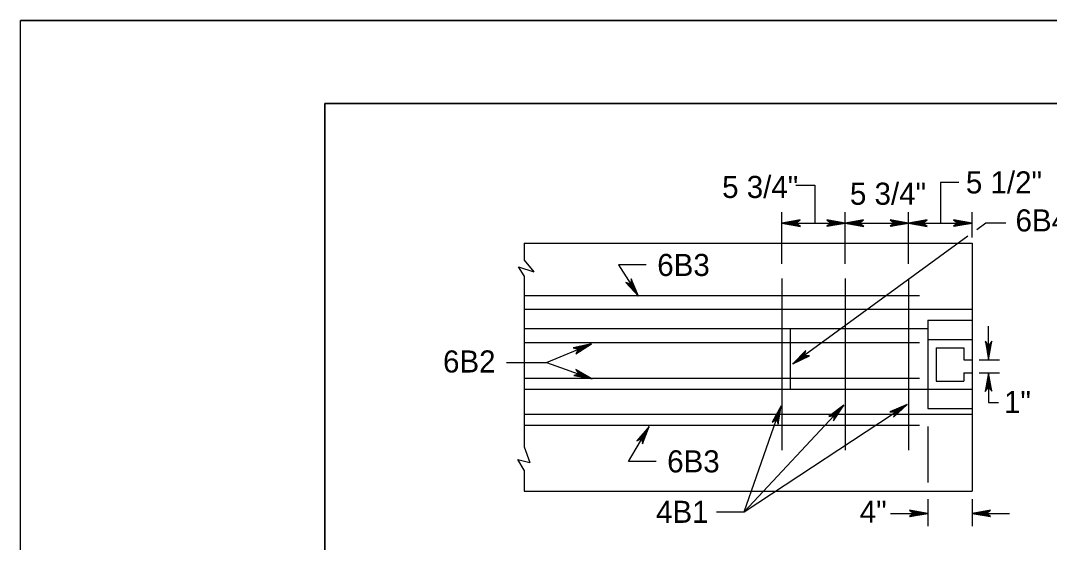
# Model space of a CAD drawing. Extents: x 499883 to 500983, y 499104 to 499764.
# Drawn here: x 499934.8 to 500121.3, y 499669.1 to 499763.6 of the extents above; entities that cross this region are included whole.
import ezdxf

# ---------------------------------------------------------------- set-up
doc = ezdxf.new("R2010")
doc.units = 0
for name, color, linetype in [('1', 7, 'Continuous'), ('24', 7, 'Continuous'), ('41', 7, 'Continuous'), ('5', 7, 'Continuous')]:
    doc.layers.add(name, color=color, linetype=linetype)

msp = doc.modelspace()

# ---------------------------------------------------------------- linework, layer by layer
at = {"layer": '1'}
for p, q in [((500982.94, 499763.64), (499934.77, 499763.64)), ((499989.94, 499748.64), (499989.94, 499118.64)), ((499989.94, 499748.64), (499989.94, 499118.64)), ((500979.94, 499748.64), (499989.94, 499748.64))]:
    msp.add_line(p, q, dxfattribs=at)
at = {"layer": '24'}
for points in [[(500072.77, 499726.96), (500076.12, 499726.37), (500075.32, 499726.96), (500076.1, 499727.54), (500072.77, 499726.96), (500072.99, 499726.97), (500076.03, 499726.41), (500075.26, 499726.97), (500075.97, 499727.5), (500073.11, 499726.98), (500073.22, 499726.96), (500075.82, 499726.5), (500075.24, 499726.97), (500075.84, 499727.42), (500073.28, 499726.96), (500073.39, 499726.98), (500075.66, 499726.57), (500075.22, 499726.96), (500075.67, 499727.37), (500073.71, 499726.98), (500073.9, 499726.98), (500075.49, 499726.65), (500075.18, 499726.95), (500075.51, 499727.28), (500073.93, 499726.96), (500074.11, 499726.95), (500075.31, 499726.74), (500075.08, 499726.98), (500075.33, 499727.21), (500074.28, 499726.96), (500074.44, 499726.94), (500075.16, 499726.8), (500075.04, 499726.97), (500075.24, 499727.15), (500074.53, 499726.96), (500075, 499726.85), (500074.93, 499726.98), (500075.14, 499727.1), (500074.65, 499726.98), (500074.96, 499726.9), (500074.83, 499727), (500074.98, 499727.06), (500074.83, 499726.97), (500074.91, 499726.95)], [(500084.26, 499726.96), (500080.91, 499727.55), (500081.71, 499726.96), (500080.93, 499726.38), (500084.26, 499726.96), (500084.04, 499726.95), (500081.01, 499727.51), (500081.77, 499726.95), (500081.06, 499726.42), (500083.92, 499726.94), (500083.81, 499726.96), (500081.21, 499727.42), (500081.79, 499726.95), (500081.19, 499726.5), (500083.76, 499726.96), (500083.64, 499726.94), (500081.37, 499727.35), (500081.82, 499726.96), (500081.36, 499726.55), (500083.32, 499726.94), (500083.13, 499726.94), (500081.54, 499727.27), (500081.85, 499726.97), (500081.52, 499726.64), (500083.1, 499726.96), (500082.92, 499726.97), (500081.72, 499727.17), (500081.95, 499726.94), (500081.7, 499726.71), (500082.76, 499726.96), (500082.59, 499726.98), (500081.87, 499727.11), (500081.99, 499726.95), (500081.79, 499726.77), (500082.5, 499726.96), (500082.03, 499727.07), (500082.1, 499726.94), (500081.89, 499726.81), (500082.38, 499726.94), (500082.07, 499727.02), (500082.2, 499726.92), (500082.05, 499726.86), (500082.2, 499726.95), (500082.13, 499726.97)], [(500084.26, 499726.96), (500087.61, 499726.37), (500086.81, 499726.96), (500087.59, 499727.54), (500084.26, 499726.96), (500084.48, 499726.97), (500087.52, 499726.41), (500086.75, 499726.97), (500087.46, 499727.5), (500084.6, 499726.98), (500084.72, 499726.96), (500087.31, 499726.5), (500086.73, 499726.97), (500087.33, 499727.42), (500084.77, 499726.96), (500084.88, 499726.98), (500087.15, 499726.57), (500086.71, 499726.96), (500087.16, 499727.37), (500085.2, 499726.98), (500085.39, 499726.98), (500086.98, 499726.65), (500086.67, 499726.95), (500087, 499727.28), (500085.42, 499726.96), (500085.6, 499726.95), (500086.8, 499726.74), (500086.57, 499726.98), (500086.82, 499727.21), (500085.77, 499726.96), (500085.94, 499726.94), (500086.65, 499726.8), (500086.54, 499726.97), (500086.73, 499727.15), (500086.02, 499726.96), (500086.49, 499726.85), (500086.42, 499726.98), (500086.63, 499727.1), (500086.14, 499726.98), (500086.45, 499726.9), (500086.32, 499727), (500086.47, 499727.06), (500086.32, 499726.97), (500086.4, 499726.95)], [(500095.75, 499726.96), (500092.4, 499727.55), (500093.2, 499726.96), (500092.42, 499726.38), (500095.75, 499726.96), (500095.53, 499726.95), (500092.5, 499727.51), (500093.27, 499726.95), (500092.56, 499726.42), (500095.41, 499726.94), (500095.3, 499726.96), (500092.7, 499727.42), (500093.28, 499726.95), (500092.68, 499726.5), (500095.25, 499726.96), (500095.14, 499726.94), (500092.86, 499727.35), (500093.31, 499726.96), (500092.86, 499726.55), (500094.81, 499726.94), (500094.62, 499726.94), (500093.03, 499727.27), (500093.34, 499726.97), (500093.01, 499726.64), (500094.59, 499726.96), (500094.41, 499726.97), (500093.22, 499727.17), (500093.45, 499726.94), (500093.2, 499726.71), (500094.25, 499726.96), (500094.08, 499726.98), (500093.36, 499727.11), (500093.48, 499726.95), (500093.28, 499726.77), (500093.99, 499726.96), (500093.52, 499727.07), (500093.59, 499726.94), (500093.38, 499726.81), (500093.87, 499726.94), (500093.57, 499727.02), (500093.69, 499726.92), (500093.55, 499726.86), (500093.69, 499726.95), (500093.62, 499726.97)], [(500095.75, 499726.96), (500099.1, 499726.37), (500098.3, 499726.96), (500099.09, 499727.54), (500095.75, 499726.96), (500095.98, 499726.97), (500099.01, 499726.41), (500098.24, 499726.97), (500098.95, 499727.5), (500096.1, 499726.98), (500096.21, 499726.96), (500098.81, 499726.5), (500098.22, 499726.97), (500098.82, 499727.42), (500096.26, 499726.96), (500096.37, 499726.98), (500098.64, 499726.57), (500098.2, 499726.96), (500098.65, 499727.37), (500096.69, 499726.98), (500096.88, 499726.98), (500098.47, 499726.65), (500098.16, 499726.95), (500098.5, 499727.28), (500096.92, 499726.96), (500097.09, 499726.95), (500098.29, 499726.74), (500098.06, 499726.98), (500098.31, 499727.21), (500097.26, 499726.96), (500097.43, 499726.94), (500098.15, 499726.8), (500098.03, 499726.97), (500098.22, 499727.15), (500097.51, 499726.96), (500097.98, 499726.85), (500097.92, 499726.98), (500098.12, 499727.1), (500097.63, 499726.98), (500097.94, 499726.9), (500097.81, 499727), (500097.96, 499727.06), (500097.81, 499726.97), (500097.89, 499726.95)], [(500107.24, 499726.96), (500103.89, 499727.55), (500104.69, 499726.96), (500103.91, 499726.38), (500107.24, 499726.96), (500107.02, 499726.95), (500103.99, 499727.51), (500104.76, 499726.95), (500104.05, 499726.42), (500106.9, 499726.94), (500106.79, 499726.96), (500104.19, 499727.42), (500104.77, 499726.95), (500104.17, 499726.5), (500106.74, 499726.96), (500106.63, 499726.94), (500104.36, 499727.35), (500104.8, 499726.96), (500104.35, 499726.55), (500106.3, 499726.94), (500106.11, 499726.94), (500104.52, 499727.27), (500104.83, 499726.97), (500104.5, 499726.64), (500106.08, 499726.96), (500105.9, 499726.97), (500104.71, 499727.17), (500104.94, 499726.94), (500104.69, 499726.71), (500105.74, 499726.96), (500105.57, 499726.98), (500104.85, 499727.11), (500104.97, 499726.95), (500104.77, 499726.77), (500105.48, 499726.96), (500105.01, 499727.07), (500105.08, 499726.94), (500104.88, 499726.81), (500105.36, 499726.94), (500105.06, 499727.02), (500105.19, 499726.92), (500105.04, 499726.86), (500105.18, 499726.95), (500105.11, 499726.97)], [(500046.76, 499713.71), (500045.47, 499716.86), (500045.4, 499715.87), (500044.49, 499716.22), (500046.76, 499713.71), (500046.64, 499713.89), (500045.49, 499716.76), (500045.43, 499715.81), (500044.6, 499716.13), (500046.57, 499713.99), (500046.52, 499714.09), (500045.52, 499716.54), (500045.44, 499715.79), (500044.73, 499716.06), (500046.49, 499714.14), (500046.42, 499714.22), (500045.55, 499716.36), (500045.46, 499715.78), (500044.87, 499715.94), (500046.25, 499714.5), (500046.15, 499714.66), (500045.57, 499716.17), (500045.48, 499715.75), (500045.02, 499715.86), (500046.14, 499714.69), (500046.05, 499714.85), (500045.59, 499715.97), (500045.52, 499715.65), (500045.19, 499715.74), (500045.96, 499714.98), (500045.88, 499715.13), (500045.61, 499715.82), (500045.54, 499715.63), (500045.29, 499715.7), (500045.82, 499715.2), (500045.67, 499715.66), (500045.59, 499715.53), (500045.37, 499715.64), (500045.74, 499715.29), (500045.64, 499715.59), (500045.63, 499715.43), (500045.5, 499715.52), (500045.66, 499715.45), (500045.63, 499715.52)], [(500110.24, 499702.21), (500110.83, 499705.56), (500110.24, 499704.76), (500109.66, 499705.55), (500110.24, 499702.21), (500110.24, 499702.44), (500110.79, 499705.47), (500110.23, 499704.7), (500109.7, 499705.41), (500110.23, 499702.56), (500110.24, 499702.67), (500110.7, 499705.27), (500110.23, 499704.68), (500109.78, 499705.28), (500110.24, 499702.72), (500110.23, 499702.83), (500110.64, 499705.1), (500110.24, 499704.66), (500109.83, 499705.11), (500110.22, 499703.15), (500110.23, 499703.34), (500110.55, 499704.93), (500110.25, 499704.62), (500109.92, 499704.96), (500110.24, 499703.38), (500110.25, 499703.56), (500110.46, 499704.75), (500110.22, 499704.52), (500110, 499704.77), (500110.24, 499703.72), (500110.26, 499703.89), (500110.4, 499704.61), (500110.23, 499704.49), (500110.06, 499704.68), (500110.24, 499703.98), (500110.35, 499704.45), (500110.23, 499704.38), (500110.1, 499704.58), (500110.22, 499704.09), (500110.3, 499704.4), (500110.2, 499704.27), (500110.14, 499704.42), (500110.23, 499704.27), (500110.25, 499704.35)], [(500038.26, 499705.08), (500034.93, 499704.35), (500035.9, 499704.11), (500035.39, 499703.27), (500038.26, 499705.08), (500038.05, 499704.99), (500035.04, 499704.35), (500035.96, 499704.13), (500035.5, 499703.37), (500037.95, 499704.93), (500037.84, 499704.9), (500035.26, 499704.35), (500035.97, 499704.13), (500035.59, 499703.48), (500037.79, 499704.88), (500037.69, 499704.83), (500035.43, 499704.34), (500035.99, 499704.15), (500035.73, 499703.6), (500037.39, 499704.7), (500037.22, 499704.63), (500035.62, 499704.33), (500036.02, 499704.17), (500035.84, 499703.74), (500037.18, 499704.63), (500037.01, 499704.58), (500035.83, 499704.31), (500036.13, 499704.18), (500035.98, 499703.88), (500036.86, 499704.5), (500036.7, 499704.46), (500035.98, 499704.31), (500036.15, 499704.21), (500036.04, 499703.97), (500036.63, 499704.41), (500036.15, 499704.33), (500036.26, 499704.24), (500036.12, 499704.04), (500036.52, 499704.35), (500036.21, 499704.3), (500036.37, 499704.26), (500036.25, 499704.15), (500036.35, 499704.29), (500036.28, 499704.27)], [(500074.75, 499701.45), (500077.8, 499702.94), (500076.81, 499702.95), (500077.1, 499703.88), (500074.75, 499701.45), (500074.92, 499701.58), (500077.7, 499702.92), (500076.75, 499702.92), (500077.01, 499703.77), (500075.01, 499701.66), (500075.11, 499701.72), (500077.49, 499702.87), (500076.74, 499702.91), (500076.95, 499703.63), (500075.15, 499701.75), (500075.23, 499701.82), (500077.31, 499702.83), (500076.72, 499702.89), (500076.85, 499703.49), (500075.5, 499702.02), (500075.65, 499702.13), (500077.13, 499702.8), (500076.7, 499702.86), (500076.77, 499703.33), (500075.69, 499702.13), (500075.84, 499702.23), (500076.92, 499702.77), (500076.6, 499702.82), (500076.67, 499703.15), (500075.96, 499702.34), (500076.11, 499702.42), (500076.77, 499702.73), (500076.58, 499702.79), (500076.63, 499703.05), (500076.17, 499702.49), (500076.61, 499702.67), (500076.48, 499702.74), (500076.57, 499702.96), (500076.26, 499702.57), (500076.55, 499702.69), (500076.39, 499702.69), (500076.47, 499702.83), (500076.41, 499702.67), (500076.48, 499702.7)], [(500038.39, 499698.76), (500035.43, 499700.44), (500035.98, 499699.62), (500035.05, 499699.33), (500038.39, 499698.76), (500038.17, 499698.83), (500035.5, 499700.37), (500036.04, 499699.59), (500035.19, 499699.33), (500038.06, 499698.86), (500037.96, 499698.91), (500035.67, 499700.22), (500036.06, 499699.58), (500035.34, 499699.36), (500037.91, 499698.93), (500037.8, 499698.95), (500035.8, 499700.1), (500036.08, 499699.58), (500035.52, 499699.35), (500037.49, 499699.06), (500037.32, 499699.13), (500035.93, 499699.97), (500036.12, 499699.58), (500035.69, 499699.38), (500037.29, 499699.15), (500037.13, 499699.22), (500036.07, 499699.82), (500036.21, 499699.52), (500035.89, 499699.39), (500036.97, 499699.27), (500036.81, 499699.34), (500036.18, 499699.71), (500036.24, 499699.52), (500036, 499699.42), (500036.73, 499699.35), (500036.32, 499699.62), (500036.34, 499699.47), (500036.11, 499699.42), (500036.61, 499699.38), (500036.35, 499699.55), (500036.43, 499699.41), (500036.27, 499699.41), (500036.44, 499699.45), (500036.38, 499699.49)], [(500110.24, 499699.82), (500109.65, 499696.47), (500110.24, 499697.27), (500110.82, 499696.49), (500110.24, 499699.82), (500110.25, 499699.6), (500109.69, 499696.57), (500110.25, 499697.33), (500110.78, 499696.62), (500110.26, 499699.48), (500110.24, 499699.37), (500109.78, 499696.77), (500110.25, 499697.35), (500110.7, 499696.75), (500110.24, 499699.32), (500110.26, 499699.2), (500109.85, 499696.93), (500110.24, 499697.38), (500110.65, 499696.92), (500110.26, 499698.88), (500110.26, 499698.69), (500109.93, 499697.1), (500110.23, 499697.41), (500110.57, 499697.08), (500110.24, 499698.66), (500110.23, 499698.48), (500110.03, 499697.28), (500110.26, 499697.51), (500110.49, 499697.26), (500110.24, 499698.32), (500110.22, 499698.15), (500110.09, 499697.43), (500110.25, 499697.55), (500110.43, 499697.35), (500110.24, 499698.06), (500110.13, 499697.59), (500110.26, 499697.66), (500110.39, 499697.45), (500110.26, 499697.94), (500110.18, 499697.63), (500110.28, 499697.76), (500110.34, 499697.61), (500110.25, 499697.76), (500110.23, 499697.69)], [(500084, 499693.99), (500081.28, 499691.95), (500082.26, 499692.13), (500082.15, 499691.16), (500084, 499693.99), (500083.86, 499693.83), (500081.38, 499691.99), (500082.31, 499692.17), (500082.21, 499691.29), (500083.78, 499693.73), (500083.69, 499693.66), (500081.58, 499692.08), (500082.32, 499692.18), (500082.24, 499691.44), (500083.66, 499693.62), (500083.59, 499693.53), (500081.74, 499692.15), (500082.33, 499692.21), (500082.32, 499691.6), (500083.37, 499693.29), (500083.24, 499693.16), (500081.92, 499692.22), (500082.35, 499692.24), (500082.37, 499691.77), (500083.21, 499693.14), (500083.08, 499693.02), (500082.11, 499692.29), (500082.44, 499692.3), (500082.44, 499691.96), (500082.98, 499692.89), (500082.85, 499692.78), (500082.26, 499692.35), (500082.46, 499692.33), (500082.45, 499692.06), (500082.8, 499692.71), (500082.4, 499692.44), (500082.54, 499692.4), (500082.49, 499692.16), (500082.73, 499692.61), (500082.47, 499692.44), (500082.63, 499692.46), (500082.57, 499692.31), (500082.6, 499692.48), (500082.54, 499692.44)], [(500095.47, 499694.12), (500092.35, 499692.77), (500093.34, 499692.72), (500093.01, 499691.8), (500095.47, 499694.12), (500095.29, 499693.99), (500092.45, 499692.79), (500093.4, 499692.75), (500093.1, 499691.91), (500095.2, 499693.92), (500095.09, 499693.87), (500092.67, 499692.83), (500093.41, 499692.76), (500093.16, 499692.05), (500095.05, 499693.84), (500094.97, 499693.77), (500092.84, 499692.86), (500093.43, 499692.78), (500093.28, 499692.19), (500094.7, 499693.59), (500094.54, 499693.49), (500093.03, 499692.88), (500093.45, 499692.8), (500093.36, 499692.34), (500094.5, 499693.48), (500094.35, 499693.39), (500093.24, 499692.91), (500093.56, 499692.84), (500093.47, 499692.51), (500094.22, 499693.29), (500094.07, 499693.22), (500093.39, 499692.93), (500093.58, 499692.86), (500093.51, 499692.61), (500094, 499693.15), (500093.55, 499692.99), (500093.68, 499692.92), (500093.57, 499692.7), (500093.91, 499693.07), (500093.61, 499692.97), (500093.78, 499692.96), (500093.69, 499692.82), (500093.76, 499692.98), (500093.68, 499692.95)], [(500072.66, 499693.86), (500071, 499690.9), (500071.82, 499691.46), (500072.11, 499690.53), (500072.66, 499693.86), (500072.6, 499693.65), (500071.07, 499690.97), (500071.85, 499691.51), (500072.11, 499690.67), (500072.57, 499693.54), (500072.51, 499693.44), (500071.22, 499691.14), (500071.85, 499691.53), (500072.08, 499690.81), (500072.5, 499693.39), (500072.48, 499693.28), (500071.34, 499691.27), (500071.85, 499691.56), (500072.09, 499690.99), (500072.37, 499692.97), (500072.31, 499692.79), (500071.47, 499691.4), (500071.86, 499691.59), (500072.06, 499691.17), (500072.28, 499692.77), (500072.21, 499692.6), (500071.62, 499691.54), (500071.92, 499691.68), (500072.05, 499691.37), (500072.17, 499692.44), (500072.09, 499692.29), (500071.73, 499691.66), (500071.92, 499691.72), (500072.02, 499691.47), (500072.08, 499692.2), (500071.82, 499691.8), (500071.96, 499691.82), (500072.02, 499691.58), (500072.06, 499692.08), (500071.88, 499691.82), (500072.02, 499691.91), (500072.03, 499691.75), (500071.99, 499691.92), (500071.95, 499691.85)], [(500048.69, 499690.13), (500046.49, 499687.54), (500047.4, 499687.93), (500047.51, 499686.96), (500048.69, 499690.13), (500048.59, 499689.93), (500046.57, 499687.6), (500047.44, 499687.98), (500047.54, 499687.1), (500048.54, 499689.82), (500048.46, 499689.74), (500046.75, 499687.73), (500047.45, 499687.99), (500047.54, 499687.25), (500048.44, 499689.69), (500048.4, 499689.59), (500046.89, 499687.84), (500047.46, 499688.02), (500047.58, 499687.42), (500048.23, 499689.31), (500048.14, 499689.14), (500047.05, 499687.94), (500047.47, 499688.05), (500047.58, 499687.6), (500048.11, 499689.12), (500048.01, 499688.98), (500047.22, 499688.05), (500047.54, 499688.13), (500047.61, 499687.8), (500047.93, 499688.83), (500047.83, 499688.69), (500047.35, 499688.14), (500047.55, 499688.16), (500047.6, 499687.9), (500047.8, 499688.61), (500047.47, 499688.26), (500047.61, 499688.25), (500047.62, 499688.01), (500047.76, 499688.5), (500047.54, 499688.27), (500047.69, 499688.33), (500047.66, 499688.17), (500047.66, 499688.35), (500047.6, 499688.29)], [(500099.25, 499674.38), (500095.9, 499674.97), (500096.7, 499674.38), (500095.92, 499673.8), (500099.25, 499674.38), (500099.03, 499674.37), (500095.99, 499674.93), (500096.76, 499674.37), (500096.05, 499673.84), (500098.91, 499674.36), (500098.8, 499674.38), (500096.2, 499674.84), (500096.78, 499674.37), (500096.18, 499673.92), (500098.74, 499674.38), (500098.63, 499674.36), (500096.36, 499674.77), (500096.8, 499674.38), (500096.35, 499673.97), (500098.31, 499674.36), (500098.12, 499674.36), (500096.53, 499674.69), (500096.84, 499674.39), (500096.51, 499674.06), (500098.09, 499674.38), (500097.91, 499674.39), (500096.71, 499674.59), (500096.94, 499674.36), (500096.69, 499674.13), (500097.74, 499674.38), (500097.58, 499674.4), (500096.86, 499674.53), (500096.98, 499674.37), (500096.78, 499674.19), (500097.49, 499674.38), (500097.02, 499674.49), (500097.09, 499674.36), (500096.88, 499674.23), (500097.37, 499674.36), (500097.06, 499674.44), (500097.19, 499674.34), (500097.04, 499674.28), (500097.19, 499674.37), (500097.11, 499674.39)], [(500107.24, 499674.38), (500110.59, 499673.79), (500109.79, 499674.38), (500110.58, 499674.96), (500107.24, 499674.38), (500107.47, 499674.39), (500110.5, 499673.83), (500109.73, 499674.39), (500110.44, 499674.92), (500107.59, 499674.4), (500107.7, 499674.38), (500110.3, 499673.92), (500109.71, 499674.39), (500110.31, 499674.84), (500107.75, 499674.38), (500107.86, 499674.4), (500110.13, 499673.99), (500109.69, 499674.38), (500110.14, 499674.79), (500108.18, 499674.4), (500108.37, 499674.4), (500109.96, 499674.07), (500109.65, 499674.37), (500109.99, 499674.7), (500108.41, 499674.38), (500108.59, 499674.37), (500109.78, 499674.16), (500109.55, 499674.4), (500109.8, 499674.63), (500108.75, 499674.38), (500108.92, 499674.36), (500109.64, 499674.23), (500109.52, 499674.39), (500109.71, 499674.57), (500109.01, 499674.38), (500109.47, 499674.27), (500109.41, 499674.4), (500109.61, 499674.52), (500109.12, 499674.4), (500109.43, 499674.32), (500109.3, 499674.42), (500109.45, 499674.48), (500109.3, 499674.39), (500109.38, 499674.37)]]:
    msp.add_lwpolyline(points, dxfattribs=at)
at = {"layer": '41'}
for points in [[(499934.77, 499763.64), (500982.94, 499763.64), (500982.94, 499103.64), (499934.77, 499103.64)], [(499989.94, 499748.64), (500979.94, 499748.64), (500979.94, 499118.64), (499989.94, 499118.64)]]:
    msp.add_lwpolyline(points, close=True, dxfattribs=at)
at = {"layer": '5'}
for p, q in [((500072.77, 499719.56), (500072.77, 499728.96)), ((500084.26, 499719.56), (500084.26, 499728.96)), ((500095.75, 499719.56), (500095.75, 499728.96)), ((500107.24, 499724.34), (500107.24, 499728.96)), ((500072.77, 499726.96), (500084.26, 499726.96)), ((500084.26, 499726.96), (500095.75, 499726.96)), ((500095.75, 499726.96), (500107.24, 499726.96)), ((500106.47, 499724.57), (500074.75, 499701.45)), ((500026.03, 499723.34), (500107.24, 499723.34)), ((500026.03, 499723.34), (500026.03, 499720.24)), ((500107.24, 499723.34), (500107.24, 499678.38)), ((500026.03, 499720.24), (500027.78, 499718.14)), ((500026.03, 499717.42), (500025.01, 499719.06)), ((500025.01, 499719.06), (500027.78, 499718.14)), ((500026.03, 499717.42), (500026.03, 499686.45)), ((500072.77, 499716.95), (500072.77, 499685.86)), ((500084.26, 499716.95), (500084.26, 499685.86)), ((500095.75, 499716.95), (500095.75, 499685.86)), ((500026.03, 499713.85), (500097.71, 499713.85)), ((500026.03, 499711.35), (500107.24, 499711.35)), ((500099.25, 499709.35), (500107.24, 499709.35)), ((500099.25, 499709.35), (500099.25, 499696.86)), ((500026.03, 499707.85), (500099.25, 499707.85)), ((500074.27, 499707.85), (500074.27, 499696.86)), ((500110.24, 499702.21), (500110.24, 499708.31)), ((500026.03, 499705.36), (500097.71, 499705.36)), ((500099.25, 499705.86), (500107.24, 499705.86)), ((500030.08, 499701.72), (500038.26, 499705.08)), ((500100.75, 499704.36), (500105.74, 499704.36)), ((500100.75, 499704.36), (500100.75, 499698.36)), ((500105.74, 499704.36), (500105.74, 499702.21)), ((500105.74, 499702.21), (500107.24, 499702.21)), ((500108.55, 499702.21), (500112.24, 499702.21)), ((500105.74, 499699.82), (500105.74, 499698.36)), ((500105.74, 499699.82), (500107.24, 499699.82)), ((500108.55, 499699.82), (500112.24, 499699.82)), ((500026.03, 499698.86), (500097.71, 499698.86)), ((500100.75, 499698.36), (500105.74, 499698.36)), ((500026.03, 499696.86), (500099.25, 499696.86)), ((500099.25, 499696.86), (500107.24, 499696.86)), ((500099.25, 499696.86), (500099.25, 499693.36)), ((500065.93, 499674.66), (500084, 499693.99)), ((500026.03, 499692.37), (500107.24, 499692.37)), ((500065.93, 499674.66), (500072.66, 499693.86)), ((500099.25, 499693.36), (500107.24, 499693.36)), ((500026.03, 499690.37), (500097.71, 499690.37)), ((500099.25, 499690.13), (500099.25, 499679.95)), ((500026.03, 499686.45), (500027.11, 499683.58)), ((500026.03, 499682.22), (500024.93, 499684.17)), ((500024.93, 499684.17), (500027.11, 499683.58)), ((500026.03, 499682.22), (500026.03, 499678.38)), ((500026.03, 499678.38), (500107.24, 499678.38)), ((500099.25, 499676.98), (500099.25, 499672.09)), ((500107.24, 499676.98), (500107.24, 499672.09)), ((500092.49, 499674.38), (500099.25, 499674.38)), ((500107.24, 499674.38), (500114.03, 499674.38))]:
    msp.add_line(p, q, dxfattribs=at)
for points in [[(500075.3, 499733.82), (500078.75, 499733.82), (500078.75, 499726.96)], [(500104.83, 499734.33), (500101.5, 499734.33), (500101.5, 499726.96)], [(500113.36, 499726.96), (500109.74, 499726.96), (500108.1, 499725.76)], [(500048.18, 499719.38), (500043.18, 499719.38), (500046.76, 499713.71)], [(500022.83, 499701.72), (500030.08, 499701.72), (500038.39, 499698.76)], [(500110.24, 499699.82), (500110.24, 499694.44), (500112.05, 499694.44)], [(500060.94, 499674.66), (500065.93, 499674.66), (500095.47, 499694.12)], [(500049.98, 499683.81), (500044.99, 499683.81), (500048.69, 499690.13)]]:
    msp.add_lwpolyline(points, dxfattribs=at)

# ---------------------------------------------------------------- texts
for s, p in [('5 3/4"', (500061.94, 499731.51)), ('5 1/2"', (500106.13, 499732.33)), ('5 3/4"', (500085.11, 499730.28)), ('6B4 & 6B5', (500115.13, 499725.45)), ('6B3', (500050.18, 499717.38)), ('6B2', (500011.35, 499699.9)), ('1"', (500113.04, 499692.56)), ('6B3', (500051.98, 499681.81)), ('4B1', (500049.96, 499672.67)), ('4"', (500086.89, 499672.69))]:
    msp.add_text(s, height=4, dxfattribs=at).set_placement(p)

doc.saveas('drawing.dxf')
